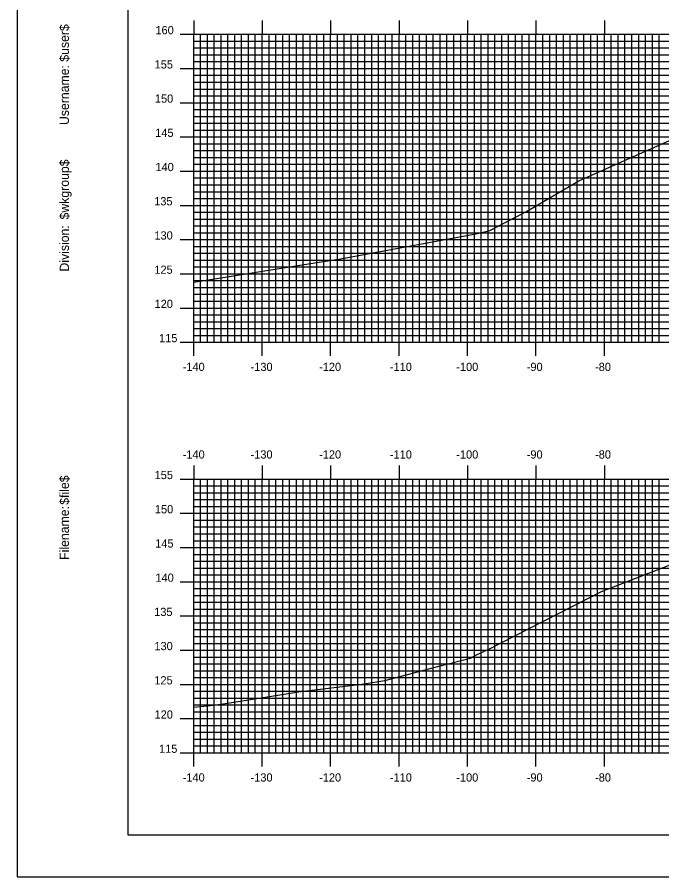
# Model space of a CAD drawing. Extents: x 860652 to 860995, y 364765 to 364985.
# Drawn here: x 860651.6 to 860745.8, y 364765.2 to 364890.8 of the extents above; entities that cross this region are included whole.
import ezdxf

# ---------------------------------------------------------------- set-up
doc = ezdxf.new("R2010")
doc.units = 0
for name, color, linetype in [('BORDER', 7, 'Continuous'), ('H_V ANNOTATION', 7, 'Continuous'), ('MAJOR', 7, 'Continuous'), ('MINOR', 7, 'Continuous'), ('PLOT BOUNDARY', 7, 'Continuous'), ('S_Roadway_Centerline', 7, 'Continuous')]:
    doc.layers.add(name, color=color, linetype=linetype)

msp = doc.modelspace()

# ---------------------------------------------------------------- linework, layer by layer
at = {"layer": 'BORDER'}
msp.add_lwpolyline([(860667.81, 364771.3), (860987.81, 364771.3), (860987.81, 364981.3), (860667.81, 364981.3)], close=True, dxfattribs=at)
at = {"layer": 'MAJOR'}
for p, q in [((860677.41, 364890.31), (860677.41, 364888.3)), ((860687.41, 364890.31), (860687.41, 364888.3)), ((860697.41, 364890.31), (860697.41, 364888.3)), ((860707.41, 364890.31), (860707.41, 364888.3)), ((860717.41, 364890.31), (860717.41, 364888.3)), ((860727.41, 364890.31), (860727.41, 364888.3)), ((860737.41, 364890.31), (860737.41, 364888.3)), ((860675.41, 364888.3), (860677.41, 364888.3)), ((860677.41, 364888.3), (860957.41, 364888.3)), ((860677.41, 364843.3), (860677.41, 364888.3)), ((860677.41, 364843.3), (860677.41, 364888.3)), ((860677.41, 364888.3), (860957.41, 364888.3)), ((860687.41, 364843.3), (860687.41, 364888.3)), ((860697.41, 364843.3), (860697.41, 364888.3)), ((860707.41, 364843.3), (860707.41, 364888.3)), ((860717.41, 364843.3), (860717.41, 364888.3)), ((860727.41, 364843.3), (860727.41, 364888.3)), ((860737.41, 364843.3), (860737.41, 364888.3)), ((860675.41, 364883.3), (860677.41, 364883.3)), ((860677.41, 364883.3), (860957.41, 364883.3)), ((860675.41, 364878.3), (860677.41, 364878.3)), ((860677.41, 364878.3), (860957.41, 364878.3)), ((860675.41, 364873.3), (860677.41, 364873.3)), ((860677.41, 364873.3), (860957.41, 364873.3)), ((860675.41, 364868.3), (860677.41, 364868.3)), ((860677.41, 364868.3), (860957.41, 364868.3)), ((860675.41, 364863.3), (860677.41, 364863.3)), ((860677.41, 364863.3), (860957.41, 364863.3)), ((860675.41, 364858.3), (860677.41, 364858.3)), ((860677.41, 364858.3), (860957.41, 364858.3)), ((860675.41, 364853.3), (860677.41, 364853.3)), ((860677.41, 364853.3), (860957.41, 364853.3)), ((860675.41, 364848.3), (860677.41, 364848.3)), ((860677.41, 364848.3), (860957.41, 364848.3)), ((860675.41, 364843.3), (860677.41, 364843.3)), ((860677.41, 364843.3), (860957.41, 364843.3)), ((860677.41, 364843.3), (860957.41, 364843.3)), ((860677.41, 364841.3), (860677.41, 364843.3)), ((860687.41, 364841.3), (860687.41, 364843.3)), ((860697.41, 364841.3), (860697.41, 364843.3)), ((860707.41, 364841.3), (860707.41, 364843.3)), ((860717.41, 364841.3), (860717.41, 364843.3)), ((860727.41, 364841.3), (860727.41, 364843.3)), ((860737.41, 364841.3), (860737.41, 364843.3)), ((860677.41, 364825.31), (860677.41, 364823.3)), ((860687.41, 364825.31), (860687.41, 364823.3)), ((860697.41, 364825.31), (860697.41, 364823.3)), ((860707.41, 364825.31), (860707.41, 364823.3)), ((860717.41, 364825.31), (860717.41, 364823.3)), ((860727.41, 364825.31), (860727.41, 364823.3)), ((860737.41, 364825.31), (860737.41, 364823.3)), ((860675.41, 364823.3), (860677.41, 364823.3)), ((860677.41, 364823.3), (860957.41, 364823.3)), ((860677.41, 364783.3), (860677.41, 364823.3)), ((860677.41, 364783.3), (860677.41, 364823.3)), ((860677.41, 364823.3), (860957.41, 364823.3)), ((860687.41, 364783.3), (860687.41, 364823.3)), ((860697.41, 364783.3), (860697.41, 364823.3)), ((860707.41, 364783.3), (860707.41, 364823.3)), ((860717.41, 364783.3), (860717.41, 364823.3)), ((860727.41, 364783.3), (860727.41, 364823.3)), ((860737.41, 364783.3), (860737.41, 364823.3)), ((860675.41, 364818.3), (860677.41, 364818.3)), ((860677.41, 364818.3), (860957.41, 364818.3)), ((860675.41, 364813.3), (860677.41, 364813.3)), ((860677.41, 364813.3), (860957.41, 364813.3)), ((860675.41, 364808.3), (860677.41, 364808.3)), ((860677.41, 364808.3), (860957.41, 364808.3)), ((860675.41, 364803.3), (860677.41, 364803.3)), ((860677.41, 364803.3), (860957.41, 364803.3)), ((860675.41, 364798.3), (860677.41, 364798.3)), ((860677.41, 364798.3), (860957.41, 364798.3)), ((860675.41, 364793.3), (860677.41, 364793.3)), ((860677.41, 364793.3), (860957.41, 364793.3)), ((860675.41, 364788.3), (860677.41, 364788.3)), ((860677.41, 364788.3), (860957.41, 364788.3)), ((860675.41, 364783.3), (860677.41, 364783.3)), ((860677.41, 364783.3), (860957.41, 364783.3)), ((860677.41, 364783.3), (860957.41, 364783.3)), ((860677.41, 364781.3), (860677.41, 364783.3)), ((860687.41, 364781.3), (860687.41, 364783.3)), ((860697.41, 364781.3), (860697.41, 364783.3)), ((860707.41, 364781.3), (860707.41, 364783.3)), ((860717.41, 364781.3), (860717.41, 364783.3)), ((860727.41, 364781.3), (860727.41, 364783.3)), ((860737.41, 364781.3), (860737.41, 364783.3))]:
    msp.add_line(p, q, dxfattribs=at)
at = {"layer": 'MINOR'}
for p, q in [((860677.41, 364887.3), (860957.41, 364887.3)), ((860677.41, 364887.3), (860679.42, 364887.3)), ((860678.41, 364843.3), (860678.41, 364888.3)), ((860679.41, 364843.3), (860679.41, 364888.3)), ((860680.41, 364843.3), (860680.41, 364888.3)), ((860681.41, 364843.3), (860681.41, 364888.3)), ((860682.41, 364843.3), (860682.41, 364888.3)), ((860683.41, 364843.3), (860683.41, 364888.3)), ((860684.41, 364843.3), (860684.41, 364888.3)), ((860685.41, 364843.3), (860685.41, 364888.3)), ((860686.41, 364843.3), (860686.41, 364888.3)), ((860688.41, 364843.3), (860688.41, 364888.3)), ((860689.41, 364843.3), (860689.41, 364888.3)), ((860690.41, 364843.3), (860690.41, 364888.3)), ((860691.41, 364843.3), (860691.41, 364888.3)), ((860692.41, 364843.3), (860692.41, 364888.3)), ((860693.41, 364843.3), (860693.41, 364888.3)), ((860694.41, 364843.3), (860694.41, 364888.3)), ((860695.41, 364843.3), (860695.41, 364888.3)), ((860696.41, 364843.3), (860696.41, 364888.3)), ((860698.41, 364843.3), (860698.41, 364888.3)), ((860699.41, 364843.3), (860699.41, 364888.3)), ((860700.41, 364843.3), (860700.41, 364888.3)), ((860701.41, 364843.3), (860701.41, 364888.3)), ((860702.41, 364843.3), (860702.41, 364888.3)), ((860703.41, 364843.3), (860703.41, 364888.3)), ((860704.41, 364843.3), (860704.41, 364888.3)), ((860705.41, 364843.3), (860705.41, 364888.3)), ((860706.41, 364843.3), (860706.41, 364888.3)), ((860708.41, 364843.3), (860708.41, 364888.3)), ((860709.41, 364843.3), (860709.41, 364888.3)), ((860710.41, 364843.3), (860710.41, 364888.3)), ((860711.41, 364843.3), (860711.41, 364888.3)), ((860712.41, 364843.3), (860712.41, 364888.3)), ((860713.41, 364843.3), (860713.41, 364888.3)), ((860714.41, 364843.3), (860714.41, 364888.3)), ((860715.41, 364843.3), (860715.41, 364888.3)), ((860716.41, 364843.3), (860716.41, 364888.3)), ((860718.41, 364843.3), (860718.41, 364888.3)), ((860719.41, 364843.3), (860719.41, 364888.3)), ((860720.41, 364843.3), (860720.41, 364888.3)), ((860721.41, 364843.3), (860721.41, 364888.3)), ((860722.41, 364843.3), (860722.41, 364888.3)), ((860723.41, 364843.3), (860723.41, 364888.3)), ((860724.41, 364843.3), (860724.41, 364888.3)), ((860725.41, 364843.3), (860725.41, 364888.3)), ((860726.41, 364843.3), (860726.41, 364888.3)), ((860728.41, 364843.3), (860728.41, 364888.3)), ((860729.41, 364843.3), (860729.41, 364888.3)), ((860730.41, 364843.3), (860730.41, 364888.3)), ((860731.41, 364843.3), (860731.41, 364888.3)), ((860732.41, 364843.3), (860732.41, 364888.3)), ((860733.41, 364843.3), (860733.41, 364888.3)), ((860734.41, 364843.3), (860734.41, 364888.3)), ((860735.41, 364843.3), (860735.41, 364888.3)), ((860736.41, 364843.3), (860736.41, 364888.3)), ((860738.41, 364843.3), (860738.41, 364888.3)), ((860739.41, 364843.3), (860739.41, 364888.3)), ((860740.41, 364843.3), (860740.41, 364888.3)), ((860741.41, 364843.3), (860741.41, 364888.3)), ((860742.41, 364843.3), (860742.41, 364888.3)), ((860743.41, 364843.3), (860743.41, 364888.3)), ((860744.41, 364843.3), (860744.41, 364888.3)), ((860745.41, 364843.3), (860745.41, 364888.3)), ((860677.41, 364886.3), (860957.41, 364886.3)), ((860677.41, 364886.3), (860679.42, 364886.3)), ((860677.41, 364885.3), (860957.41, 364885.3)), ((860677.41, 364885.3), (860679.42, 364885.3)), ((860677.41, 364884.3), (860957.41, 364884.3)), ((860677.41, 364884.3), (860679.42, 364884.3)), ((860677.41, 364882.3), (860957.41, 364882.3)), ((860677.41, 364882.3), (860679.42, 364882.3)), ((860677.41, 364881.3), (860957.41, 364881.3)), ((860677.41, 364881.3), (860679.42, 364881.3)), ((860677.41, 364880.3), (860957.41, 364880.3)), ((860677.41, 364880.3), (860679.42, 364880.3)), ((860677.41, 364879.3), (860957.41, 364879.3)), ((860677.41, 364879.3), (860679.42, 364879.3)), ((860677.41, 364877.3), (860957.41, 364877.3)), ((860677.41, 364877.3), (860679.42, 364877.3)), ((860677.41, 364876.3), (860957.41, 364876.3)), ((860677.41, 364876.3), (860679.42, 364876.3)), ((860677.41, 364875.3), (860957.41, 364875.3)), ((860677.41, 364875.3), (860679.42, 364875.3)), ((860677.41, 364874.3), (860957.41, 364874.3)), ((860677.41, 364874.3), (860679.42, 364874.3)), ((860677.41, 364872.3), (860957.41, 364872.3)), ((860677.41, 364872.3), (860679.42, 364872.3)), ((860677.41, 364871.3), (860957.41, 364871.3)), ((860677.41, 364871.3), (860679.42, 364871.3)), ((860677.41, 364870.3), (860957.41, 364870.3)), ((860677.41, 364870.3), (860679.42, 364870.3)), ((860677.41, 364869.3), (860957.41, 364869.3)), ((860677.41, 364869.3), (860679.42, 364869.3)), ((860677.41, 364867.3), (860957.41, 364867.3)), ((860677.41, 364867.3), (860679.42, 364867.3)), ((860677.41, 364866.3), (860957.41, 364866.3)), ((860677.41, 364866.3), (860679.42, 364866.3)), ((860677.41, 364865.3), (860957.41, 364865.3)), ((860677.41, 364865.3), (860679.42, 364865.3)), ((860677.41, 364864.3), (860957.41, 364864.3)), ((860677.41, 364864.3), (860679.42, 364864.3)), ((860677.41, 364862.3), (860957.41, 364862.3)), ((860677.41, 364862.3), (860679.42, 364862.3)), ((860677.41, 364861.3), (860957.41, 364861.3)), ((860677.41, 364861.3), (860679.42, 364861.3)), ((860677.41, 364860.3), (860957.41, 364860.3)), ((860677.41, 364860.3), (860679.42, 364860.3)), ((860677.41, 364859.3), (860957.41, 364859.3)), ((860677.41, 364859.3), (860679.42, 364859.3)), ((860677.41, 364857.3), (860957.41, 364857.3)), ((860677.41, 364857.3), (860679.42, 364857.3)), ((860677.41, 364856.3), (860957.41, 364856.3)), ((860677.41, 364856.3), (860679.42, 364856.3)), ((860677.41, 364855.3), (860957.41, 364855.3)), ((860677.41, 364855.3), (860679.42, 364855.3)), ((860677.41, 364854.3), (860957.41, 364854.3)), ((860677.41, 364854.3), (860679.42, 364854.3)), ((860677.41, 364852.3), (860957.41, 364852.3)), ((860677.41, 364852.3), (860679.42, 364852.3)), ((860677.41, 364851.3), (860957.41, 364851.3)), ((860677.41, 364851.3), (860679.42, 364851.3)), ((860677.41, 364850.3), (860957.41, 364850.3)), ((860677.41, 364850.3), (860679.42, 364850.3)), ((860677.41, 364849.3), (860957.41, 364849.3)), ((860677.41, 364849.3), (860679.42, 364849.3)), ((860677.41, 364847.3), (860957.41, 364847.3)), ((860677.41, 364847.3), (860679.42, 364847.3)), ((860677.41, 364846.3), (860957.41, 364846.3)), ((860677.41, 364846.3), (860679.42, 364846.3)), ((860677.41, 364845.3), (860957.41, 364845.3)), ((860677.41, 364845.3), (860679.42, 364845.3)), ((860677.41, 364844.3), (860957.41, 364844.3)), ((860677.41, 364844.3), (860679.42, 364844.3)), ((860678.41, 364783.3), (860678.41, 364823.3)), ((860679.41, 364783.3), (860679.41, 364823.3)), ((860680.41, 364783.3), (860680.41, 364823.3)), ((860681.41, 364783.3), (860681.41, 364823.3)), ((860682.41, 364783.3), (860682.41, 364823.3)), ((860683.41, 364783.3), (860683.41, 364823.3)), ((860684.41, 364783.3), (860684.41, 364823.3)), ((860685.41, 364783.3), (860685.41, 364823.3)), ((860686.41, 364783.3), (860686.41, 364823.3)), ((860688.41, 364783.3), (860688.41, 364823.3)), ((860689.41, 364783.3), (860689.41, 364823.3)), ((860690.41, 364783.3), (860690.41, 364823.3)), ((860691.41, 364783.3), (860691.41, 364823.3)), ((860692.41, 364783.3), (860692.41, 364823.3)), ((860693.41, 364783.3), (860693.41, 364823.3)), ((860694.41, 364783.3), (860694.41, 364823.3)), ((860695.41, 364783.3), (860695.41, 364823.3)), ((860696.41, 364783.3), (860696.41, 364823.3)), ((860698.41, 364783.3), (860698.41, 364823.3)), ((860699.41, 364783.3), (860699.41, 364823.3)), ((860700.41, 364783.3), (860700.41, 364823.3)), ((860701.41, 364783.3), (860701.41, 364823.3)), ((860702.41, 364783.3), (860702.41, 364823.3)), ((860703.41, 364783.3), (860703.41, 364823.3)), ((860704.41, 364783.3), (860704.41, 364823.3)), ((860705.41, 364783.3), (860705.41, 364823.3)), ((860706.41, 364783.3), (860706.41, 364823.3)), ((860708.41, 364783.3), (860708.41, 364823.3)), ((860709.41, 364783.3), (860709.41, 364823.3)), ((860710.41, 364783.3), (860710.41, 364823.3)), ((860711.41, 364783.3), (860711.41, 364823.3)), ((860712.41, 364783.3), (860712.41, 364823.3)), ((860713.41, 364783.3), (860713.41, 364823.3)), ((860714.41, 364783.3), (860714.41, 364823.3)), ((860715.41, 364783.3), (860715.41, 364823.3)), ((860716.41, 364783.3), (860716.41, 364823.3)), ((860718.41, 364783.3), (860718.41, 364823.3)), ((860719.41, 364783.3), (860719.41, 364823.3)), ((860720.41, 364783.3), (860720.41, 364823.3)), ((860721.41, 364783.3), (860721.41, 364823.3)), ((860722.41, 364783.3), (860722.41, 364823.3)), ((860723.41, 364783.3), (860723.41, 364823.3)), ((860724.41, 364783.3), (860724.41, 364823.3)), ((860725.41, 364783.3), (860725.41, 364823.3)), ((860726.41, 364783.3), (860726.41, 364823.3)), ((860728.41, 364783.3), (860728.41, 364823.3)), ((860729.41, 364783.3), (860729.41, 364823.3)), ((860730.41, 364783.3), (860730.41, 364823.3)), ((860731.41, 364783.3), (860731.41, 364823.3)), ((860732.41, 364783.3), (860732.41, 364823.3)), ((860733.41, 364783.3), (860733.41, 364823.3)), ((860734.41, 364783.3), (860734.41, 364823.3)), ((860735.41, 364783.3), (860735.41, 364823.3)), ((860736.41, 364783.3), (860736.41, 364823.3)), ((860738.41, 364783.3), (860738.41, 364823.3)), ((860739.41, 364783.3), (860739.41, 364823.3)), ((860740.41, 364783.3), (860740.41, 364823.3)), ((860741.41, 364783.3), (860741.41, 364823.3)), ((860742.41, 364783.3), (860742.41, 364823.3)), ((860743.41, 364783.3), (860743.41, 364823.3)), ((860744.41, 364783.3), (860744.41, 364823.3)), ((860745.41, 364783.3), (860745.41, 364823.3)), ((860677.41, 364822.3), (860957.41, 364822.3)), ((860677.41, 364822.3), (860679.42, 364822.3)), ((860677.41, 364821.3), (860957.41, 364821.3)), ((860677.41, 364821.3), (860679.42, 364821.3)), ((860677.41, 364820.3), (860957.41, 364820.3)), ((860677.41, 364820.3), (860679.42, 364820.3)), ((860677.41, 364819.3), (860957.41, 364819.3)), ((860677.41, 364819.3), (860679.42, 364819.3)), ((860677.41, 364817.3), (860957.41, 364817.3)), ((860677.41, 364817.3), (860679.42, 364817.3)), ((860677.41, 364816.3), (860957.41, 364816.3)), ((860677.41, 364816.3), (860679.42, 364816.3)), ((860677.41, 364815.3), (860957.41, 364815.3)), ((860677.41, 364815.3), (860679.42, 364815.3)), ((860677.41, 364814.3), (860957.41, 364814.3)), ((860677.41, 364814.3), (860679.42, 364814.3)), ((860677.41, 364812.3), (860957.41, 364812.3)), ((860677.41, 364812.3), (860679.42, 364812.3)), ((860677.41, 364811.3), (860957.41, 364811.3)), ((860677.41, 364811.3), (860679.42, 364811.3)), ((860677.41, 364810.3), (860957.41, 364810.3)), ((860677.41, 364810.3), (860679.42, 364810.3)), ((860677.41, 364809.3), (860957.41, 364809.3)), ((860677.41, 364809.3), (860679.42, 364809.3)), ((860677.41, 364807.3), (860957.41, 364807.3)), ((860677.41, 364807.3), (860679.42, 364807.3)), ((860677.41, 364806.3), (860957.41, 364806.3)), ((860677.41, 364806.3), (860679.42, 364806.3)), ((860677.41, 364805.3), (860957.41, 364805.3)), ((860677.41, 364805.3), (860679.42, 364805.3)), ((860677.41, 364804.3), (860957.41, 364804.3)), ((860677.41, 364804.3), (860679.42, 364804.3)), ((860677.41, 364802.3), (860957.41, 364802.3)), ((860677.41, 364802.3), (860679.42, 364802.3)), ((860677.41, 364801.3), (860957.41, 364801.3)), ((860677.41, 364801.3), (860679.42, 364801.3)), ((860677.41, 364800.3), (860957.41, 364800.3)), ((860677.41, 364800.3), (860679.42, 364800.3)), ((860677.41, 364799.3), (860957.41, 364799.3)), ((860677.41, 364799.3), (860679.42, 364799.3)), ((860677.41, 364797.3), (860957.41, 364797.3)), ((860677.41, 364797.3), (860679.42, 364797.3)), ((860677.41, 364796.3), (860957.41, 364796.3)), ((860677.41, 364796.3), (860679.42, 364796.3)), ((860677.41, 364795.3), (860957.41, 364795.3)), ((860677.41, 364795.3), (860679.42, 364795.3)), ((860677.41, 364794.3), (860957.41, 364794.3)), ((860677.41, 364794.3), (860679.42, 364794.3)), ((860677.41, 364792.3), (860957.41, 364792.3)), ((860677.41, 364792.3), (860679.42, 364792.3)), ((860677.41, 364791.3), (860957.41, 364791.3)), ((860677.41, 364791.3), (860679.42, 364791.3)), ((860677.41, 364790.3), (860957.41, 364790.3)), ((860677.41, 364790.3), (860679.42, 364790.3)), ((860677.41, 364789.3), (860957.41, 364789.3)), ((860677.41, 364789.3), (860679.42, 364789.3)), ((860677.41, 364787.3), (860957.41, 364787.3)), ((860677.41, 364787.3), (860679.42, 364787.3)), ((860677.41, 364786.3), (860957.41, 364786.3)), ((860677.41, 364786.3), (860679.42, 364786.3)), ((860677.41, 364785.3), (860957.41, 364785.3)), ((860677.41, 364785.3), (860679.42, 364785.3)), ((860677.41, 364784.3), (860957.41, 364784.3)), ((860677.41, 364784.3), (860679.42, 364784.3))]:
    msp.add_line(p, q, dxfattribs=at)
at = {"layer": 'PLOT BOUNDARY'}
msp.add_lwpolyline([(860651.63, 364765.18), (860991.63, 364765.18), (860991.63, 364985.18), (860651.63, 364985.18)], close=True, dxfattribs=at)
at = {"layer": 'S_Roadway_Centerline'}
for points in [[(860677.41, 364852.1), (860692.64, 364854.52), (860698.56, 364855.43), (860699.37, 364855.56), (860718.89, 364859.17), (860720.68, 364859.64), (860725.95, 364862.36), (860733.66, 364866.88), (860744.73, 364871.79), (860754.16, 364876)], [(860677.41, 364789.96), (860680.37, 364790.27), (860682.37, 364790.54), (860693.08, 364792.24), (860701.96, 364793.32), (860705.35, 364793.85), (860713.62, 364796.06), (860717.82, 364797.14), (860718.73, 364797.6), (860720.31, 364798.35), (860736.99, 364806.86), (860748.76, 364811.46)]]:
    msp.add_lwpolyline(points, dxfattribs=at)

# ---------------------------------------------------------------- texts
at = {"layer": 'BORDER'}
for s, p in [('$user$', (860659.18, 364884.29)), ('Username:', (860659.18, 364875.04)), ('$wkgroup$', (860659.18, 364861.24)), ('Division:', (860659.18, 364853.63)), ('$file$', (860659.18, 364819.55)), ('Filename:', (860659.18, 364811.5))]:
    msp.add_text(s, height=1.339, rotation=90, dxfattribs=at).set_placement(p)
at = {"layer": 'H_V ANNOTATION'}
for s, p in [('160', (860671.82, 364888.3)), ('155', (860671.7, 364883.3)), ('150', (860671.74, 364878.3)), ('145', (860671.79, 364873.3)), ('140', (860671.82, 364868.3)), ('135', (860671.64, 364863.3)), ('130', (860671.67, 364858.3)), ('125', (860671.66, 364853.3)), ('120', (860671.69, 364848.3)), ('115', (860672.35, 364843.3)), ('-140', (860675.8, 364839.1)), ('-130', (860685.72, 364839.1)), ('-120', (860695.73, 364839.1)), ('-110', (860706.07, 364839.1)), ('-100', (860715.77, 364839.1)), ('-90', (860726.06, 364839.1)), ('-80', (860736.04, 364839.1)), ('-140', (860675.8, 364826.3)), ('-130', (860685.72, 364826.3)), ('-120', (860695.73, 364826.3)), ('-110', (860706.07, 364826.3)), ('-100', (860715.77, 364826.3)), ('-90', (860726.06, 364826.3)), ('-80', (860736.04, 364826.3)), ('155', (860671.7, 364823.3)), ('150', (860671.74, 364818.3)), ('145', (860671.79, 364813.3)), ('140', (860671.82, 364808.3)), ('135', (860671.64, 364803.3)), ('130', (860671.67, 364798.3)), ('125', (860671.66, 364793.3)), ('120', (860671.69, 364788.3)), ('115', (860672.35, 364783.3)), ('-140', (860675.8, 364779.1)), ('-130', (860685.72, 364779.1)), ('-120', (860695.73, 364779.1)), ('-110', (860706.07, 364779.1)), ('-100', (860715.77, 364779.1)), ('-90', (860726.06, 364779.1)), ('-80', (860736.04, 364779.1))]:
    msp.add_text(s, height=1.2, dxfattribs=at).set_placement(p)
at = {"layer": 'MAJOR'}
for p in [(860677.4, 364843.3), (860677.4, 364783.3)]:
    msp.add_text('-', height=0.012, dxfattribs=at).set_placement(p)

doc.saveas('drawing.dxf')
